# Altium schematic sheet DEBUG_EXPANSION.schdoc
size 127 x 101 mm
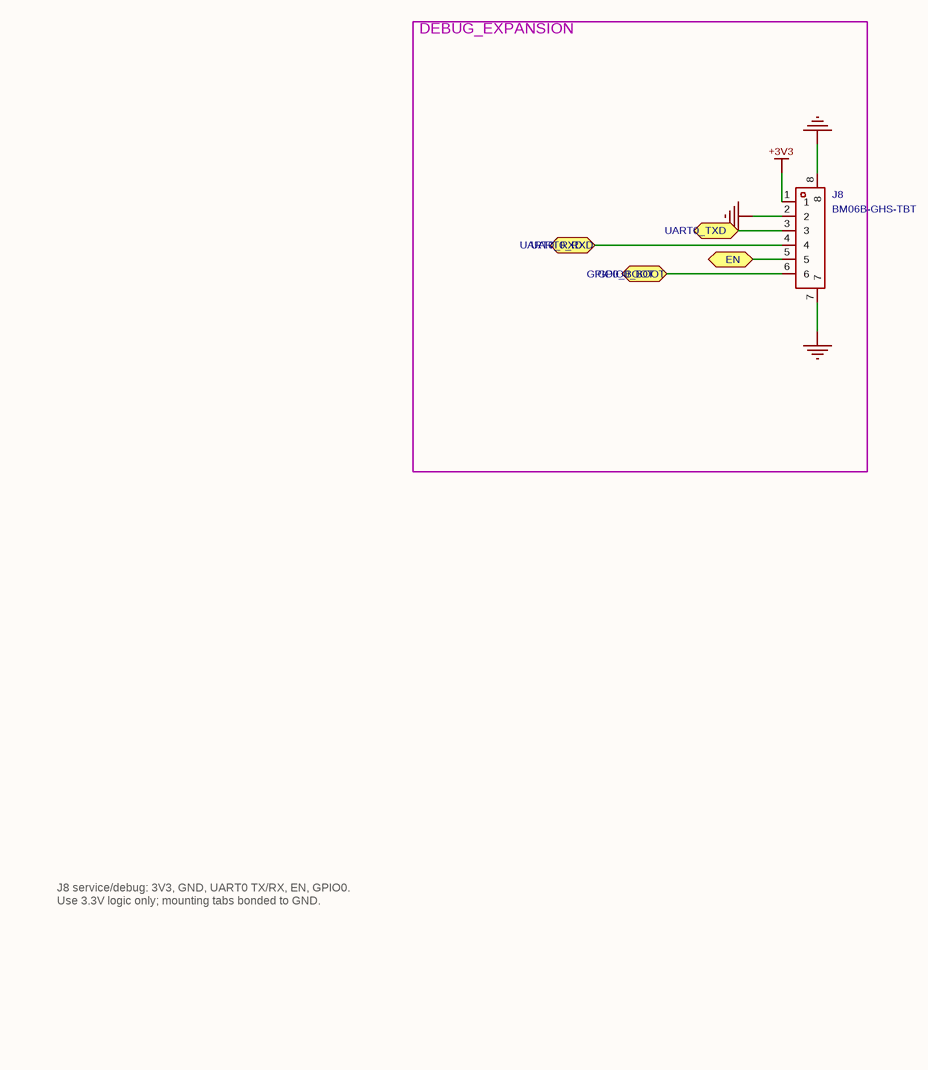
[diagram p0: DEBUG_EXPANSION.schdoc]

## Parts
J8  BM06B-GHS-TBT  [CONN-SMD_6P-P1.25_BM06B-GHS-TBT]

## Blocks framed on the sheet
DEBUG_EXPANSION: J8

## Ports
EN (bidir), GPIO0_BOOT (bidir), UART0_RXD (bidir), UART0_TXD (bidir)

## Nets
+3V3: J8.1
GND: J8.2 J8.7 J8.8
EN: J8.5 ; port EN
GPIO0_BOOT: J8.6 ; port GPIO0_BOOT
UART0_RXD: J8.4 ; port UART0_RXD
UART0_TXD: J8.3 ; port UART0_TXD

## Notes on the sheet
- J8 service/debug: 3V3, GND, UART0 TX/RX, EN, GPIO0.
  Use 3.3V logic only; mounting tabs bonded to GND.

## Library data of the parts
J8 = BM06B-GHS-TBT: Manufacturer: JST; Add into BOM: yes; ModelId: 52206651fb4a45e7ba7c1260fec4913a0819f05c4eef4c71ace90d822a990e87; ModelTransform: 423.2275,195.2752,0,0,0,0,-0.002,-15.075,0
